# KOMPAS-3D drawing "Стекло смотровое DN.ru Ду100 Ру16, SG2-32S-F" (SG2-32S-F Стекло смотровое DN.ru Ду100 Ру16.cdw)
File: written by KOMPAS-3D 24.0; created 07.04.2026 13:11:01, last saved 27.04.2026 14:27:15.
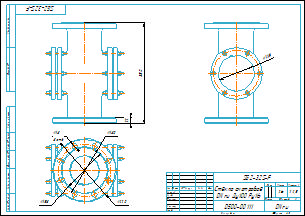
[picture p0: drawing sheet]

Document properties: Автор: Main; Форматы листов документа: A3; Полное имя файла: SG2-32S-FСтекло смотровое DN.ru Ду100 Ру16.m3d; Масса: 26; Наименование: Стекло смотровое DN.ru Ду100 Ру16; Количество листов документа: 1; Примечание: D500-00111

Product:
- Body: Тело 1  | qty 1
    Масса: 25.876303
- Part/product: Стекло смотровое DN.ru Ду100 Ру16  | designation SG2-32S-F
    Масса: 26
    Раздел спецификации: Прочие изделия
    Примечание: D500-00111

Views: Проекционный вид 3
Referenced files in D:\DN.ru Аутсерс\Стекло смотровое DN.ru\Стекло смотровое DN.ru SG2-34G-F тип В ГОСТ 21836-2021 Ду100 Ру16, углеродистая сталь, фланцевое\: SG2-34G-F тип В Стекло смотровое DN.ru Ду100 Ру16.m3d, SG2-34G-F тип ВСтекло смотровое DN.ru Ду100 Ру16.cdw
Referenced files in D:\DN.ru Аутсерс\Стекло смотровое DN.ru\SG2-32S-F Стекло смотровое DN.ru Ду100 Ру16\: SG2-32S-FСтекло смотровое DN.ru Ду100 Ру16.m3d
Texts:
  SG2-32S-F
  Стекло смотровое
  DN.ru Ду100 Ру16
  Стекло смотровое DN.ru Ду100 Ру16
  SG2-32S-F Стекло смотровое DN.ru Ду100 Ру16
Dimensions and other numbers on the sheet: 0; 3; 4; 125; 1:2,5; 1; 2; 26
